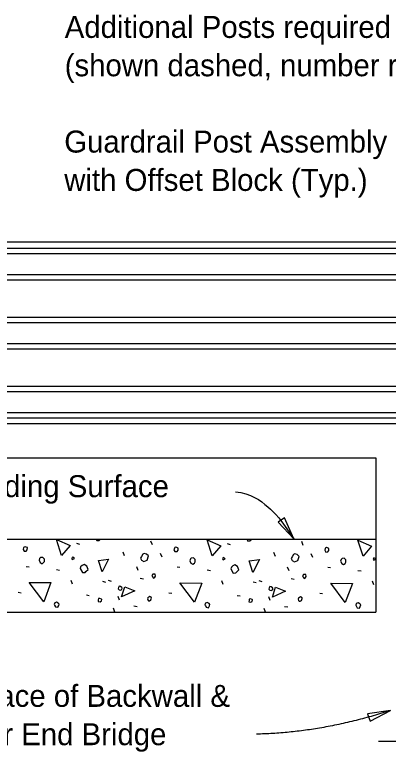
# Model space of a CAD drawing. Extents: x 21587 to 21656.3, y 56114 to 56157.2.
# Drawn here: x 21610.17 to 21613.6, y 56132.08 to 56138.87 of the extents above; entities that cross this region are included whole.
import ezdxf

# ---------------------------------------------------------------- set-up
doc = ezdxf.new("R2010")
doc.units = 0
for name, color, linetype in [('AdhocPoint_dp', 7, 'Continuous'), ('Border', 7, 'Continuous'), ('PlotBorder_dp', 7, 'Continuous'), ('SheetBorder_dp', 7, 'Continuous'), ('TextMisc', 7, 'Continuous')]:
    doc.layers.add(name, color=color, linetype=linetype)

msp = doc.modelspace()

# ---------------------------------------------------------------- linework, layer by layer
at = {"layer": 'AdhocPoint_dp'}
for p, q in [((21607.3117, 56134.8009), (21613.4854, 56134.8009)), ((21613.4854, 56134.8008), (21613.4854, 56133.3842)), ((21613.4854, 56134.0509), (21607.3117, 56134.0509)), ((21607.3117, 56133.3843), (21613.4854, 56133.3843))]:
    msp.add_line(p, q, dxfattribs=at)
at = {"layer": 'Border'}
for p, q in [((21619.5663, 56136.7801), (21607.3117, 56136.7801)), ((21607.3117, 56136.7246), (21619.5663, 56136.7246)), ((21607.3117, 56136.6764), (21619.5663, 56136.6764)), ((21607.3117, 56136.4835), (21619.5663, 56136.4835)), ((21607.3117, 56136.4353), (21619.5663, 56136.4353)), ((21607.3117, 56136.0914), (21619.5663, 56136.0914)), ((21607.3117, 56136.0431), (21619.5663, 56136.0431)), ((21607.3117, 56135.8503), (21619.5663, 56135.8503)), ((21607.3117, 56135.8022), (21619.5663, 56135.8022)), ((21607.3117, 56135.4582), (21619.5663, 56135.4582)), ((21607.3117, 56135.41), (21619.5663, 56135.41)), ((21607.3117, 56135.2172), (21619.5663, 56135.2172)), ((21607.3117, 56135.169), (21619.5663, 56135.169)), ((21619.5663, 56135.1134), (21607.3117, 56135.1134))]:
    msp.add_line(p, q, dxfattribs=at)
at = {"layer": 'PlotBorder_dp'}
for points in [[(21612.7308, 56134.0576), (21612.6444, 56134.2503), (21612.5857, 56134.211)], [(21613.6179, 56132.4823), (21613.4091, 56132.4504), (21613.4313, 56132.3834)]]:
    msp.add_lwpolyline(points, close=True, dxfattribs=at)
msp.add_lwpolyline([(21614.708, 56132.1964), (21614.1994, 56132.1964), (21614.1994, 56132.0801), (21614.1, 56132.3051), (21614.1, 56132.1964), (21613.508, 56132.1964)], dxfattribs=at)
for points, degree in [([(21612.194, 56134.4896), (21612.3358, 56134.4753), (21612.5127, 56134.3451), (21612.6101, 56134.2379), (21612.7308, 56134.0575)], 3), ([(21613.6179, 56132.4823), (21613.0032, 56132.2789), (21612.3886, 56132.2639)], 2)]:
    msp.add_open_spline(points, degree=degree, dxfattribs=at)
at = {"layer": 'TextMisc'}
for p, q in [((21611.4329, 56134.0008), (21611.4187, 56134.0362)), ((21612.8175, 56133.9973), (21612.8034, 56134.0326)), ((21610.7346, 56134.0167), (21610.7629, 56134.0096)), ((21612.1193, 56134.0132), (21612.1476, 56134.0061)), ((21611.1765, 56133.9), (21611.1624, 56133.9354)), ((21611.5206, 56133.8883), (21611.5065, 56133.9237)), ((21612.5612, 56133.8965), (21612.5471, 56133.9319)), ((21612.9053, 56133.8848), (21612.8912, 56133.9201)), ((21610.2738, 56133.8034), (21610.2986, 56133.7999)), ((21610.5496, 56133.7752), (21610.5797, 56133.7699)), ((21611.302, 56133.7675), (21611.2897, 56133.801)), ((21611.6585, 56133.7999), (21611.6833, 56133.7964)), ((21611.9343, 56133.7716), (21611.9643, 56133.7663)), ((21612.6867, 56133.7639), (21612.6743, 56133.7975)), ((21613.0432, 56133.7964), (21613.0679, 56133.7928)), ((21613.319, 56133.7681), (21613.349, 56133.7628)), ((21611.3209, 56133.6956), (21611.3509, 56133.6903)), ((21612.7055, 56133.6921), (21612.7356, 56133.6868)), ((21610.6981, 56133.6408), (21610.6857, 56133.6744)), ((21610.9721, 56133.6673), (21611.0004, 56133.6603)), ((21611.0245, 56133.6773), (21611.0528, 56133.6702)), ((21612.0828, 56133.6373), (21612.0704, 56133.6709)), ((21612.3568, 56133.6638), (21612.3851, 56133.6567)), ((21612.4092, 56133.6738), (21612.4375, 56133.6667)), ((21613.4674, 56133.6337), (21613.4551, 56133.6673)), ((21610.1996, 56133.5666), (21610.2261, 56133.5613)), ((21611.5843, 56133.563), (21611.6108, 56133.5577)), ((21612.9689, 56133.5595), (21612.9955, 56133.5542)), ((21610.8254, 56133.5418), (21610.8519, 56133.5365)), ((21611.1306, 56133.4947), (21611.1182, 56133.5283)), ((21612.21, 56133.5383), (21612.2366, 56133.533)), ((21612.5152, 56133.4912), (21612.5029, 56133.5248)), ((21611.0881, 56133.3851), (21611.074, 56133.4205)), ((21611.2608, 56133.4411), (21611.2926, 56133.4375)), ((21612.6454, 56133.4375), (21612.6773, 56133.434)), ((21612.4717, 56133.3843), (21612.4587, 56133.4169))]:
    msp.add_line(p, q, dxfattribs=at)
for points in [[(21610.5973, 56133.9042), (21610.5496, 56134.0509), (21610.6751, 56133.9961), (21610.5973, 56133.9042)], [(21610.9179, 56134.0509), (21610.922, 56134.0415), (21610.9184, 56134.045)], [(21610.922, 56134.0415), (21610.9432, 56134.0415), (21610.9527, 56134.0509)], [(21611.982, 56133.9007), (21611.9343, 56134.0474), (21612.0598, 56133.9926), (21611.982, 56133.9007)], [(21612.3017, 56134.0509), (21612.3013, 56134.0503), (21612.3067, 56134.0379), (21612.3031, 56134.0415)], [(21612.3067, 56134.0379), (21612.3279, 56134.0379), (21612.3385, 56134.0485), (21612.3378, 56134.0509)], [(21613.3667, 56133.8971), (21613.319, 56134.0439), (21613.4445, 56133.9891), (21613.3667, 56133.8971)], [(21610.2455, 56133.959), (21610.2544, 56133.9431), (21610.2738, 56133.9449), (21610.2827, 56133.9572), (21610.2844, 56133.9767), (21610.2721, 56133.982), (21610.2632, 56133.9838), (21610.2526, 56133.9802), (21610.2491, 56133.9767), (21610.2455, 56133.959)], [(21611.6302, 56133.9555), (21611.6391, 56133.9396), (21611.6585, 56133.9413), (21611.6673, 56133.9537), (21611.6691, 56133.9731), (21611.6567, 56133.9785), (21611.6479, 56133.9802), (21611.6373, 56133.9767), (21611.6338, 56133.9731), (21611.6302, 56133.9555)], [(21613.0149, 56133.9519), (21613.0237, 56133.936), (21613.0432, 56133.9378), (21613.052, 56133.9502), (21613.0538, 56133.9696), (21613.0414, 56133.9749), (21613.0326, 56133.9767), (21613.022, 56133.9731), (21613.0184, 56133.9696), (21613.0149, 56133.9519)], [(21611.3303, 56133.8629), (21611.3533, 56133.8505), (21611.3834, 56133.8629), (21611.3957, 56133.9), (21611.3781, 56133.9177), (21611.3551, 56133.923), (21611.3445, 56133.916), (21611.3321, 56133.8965), (21611.3233, 56133.8806), (21611.3303, 56133.8629)], [(21612.715, 56133.8594), (21612.738, 56133.847), (21612.768, 56133.8594), (21612.7804, 56133.8965), (21612.7627, 56133.9142), (21612.7398, 56133.9195), (21612.7291, 56133.9124), (21612.7168, 56133.893), (21612.7079, 56133.8771), (21612.715, 56133.8594)], [(21610.3905, 56133.86), (21610.4011, 56133.8388), (21610.4188, 56133.8282), (21610.4329, 56133.8388), (21610.44, 56133.8494), (21610.44, 56133.8706), (21610.4241, 56133.8865), (21610.4046, 56133.8848), (21610.3958, 56133.8759), (21610.3905, 56133.86)], [(21610.6963, 56133.8689), (21610.7158, 56133.8777), (21610.7087, 56133.8848), (21610.6963, 56133.8901), (21610.691, 56133.8777), (21610.6963, 56133.8689)], [(21610.9697, 56133.7533), (21610.9361, 56133.8576), (21611.0298, 56133.87), (21610.9697, 56133.7533)], [(21611.7752, 56133.8565), (21611.7858, 56133.8353), (21611.8035, 56133.8247), (21611.8176, 56133.8353), (21611.8247, 56133.8459), (21611.8247, 56133.8671), (21611.8088, 56133.883), (21611.7893, 56133.8812), (21611.7805, 56133.8724), (21611.7752, 56133.8565)], [(21612.081, 56133.8653), (21612.1004, 56133.8742), (21612.0934, 56133.8812), (21612.081, 56133.8865), (21612.0757, 56133.8742), (21612.081, 56133.8653)], [(21612.3544, 56133.7498), (21612.3208, 56133.8541), (21612.4145, 56133.8665), (21612.3544, 56133.7498)], [(21613.1599, 56133.8529), (21613.1705, 56133.8317), (21613.1881, 56133.8211), (21613.2023, 56133.8317), (21613.2094, 56133.8423), (21613.2094, 56133.8635), (21613.1934, 56133.8795), (21613.174, 56133.8777), (21613.1652, 56133.8689), (21613.1599, 56133.8529)], [(21613.4657, 56133.8618), (21613.4851, 56133.8706), (21613.4781, 56133.8777), (21613.4657, 56133.883), (21613.4604, 56133.8706), (21613.4657, 56133.8618)], [(21610.767, 56133.784), (21610.79, 56133.7469), (21610.813, 56133.7486), (21610.8218, 56133.7575), (21610.8413, 56133.7769), (21610.8289, 56133.807), (21610.8042, 56133.8211), (21610.7865, 56133.814), (21610.7723, 56133.7999), (21610.767, 56133.784)], [(21612.1517, 56133.7805), (21612.1747, 56133.7433), (21612.1977, 56133.7451), (21612.2065, 56133.7539), (21612.226, 56133.7734), (21612.2136, 56133.8034), (21612.1888, 56133.8176), (21612.1712, 56133.8105), (21612.157, 56133.7964), (21612.1517, 56133.7805)], [(21611.4322, 56133.708), (21611.4428, 56133.6974), (21611.4534, 56133.7044), (21611.4605, 56133.7151), (21611.457, 56133.7327), (21611.4481, 56133.7345), (21611.4358, 56133.7327), (21611.4252, 56133.7221), (21611.4322, 56133.708)], [(21612.8169, 56133.7044), (21612.8275, 56133.6938), (21612.8381, 56133.7009), (21612.8452, 56133.7115), (21612.8417, 56133.7292), (21612.8328, 56133.731), (21612.8204, 56133.7292), (21612.8098, 56133.7186), (21612.8169, 56133.7044)], [(21610.4347, 56133.4799), (21610.3003, 56133.6567), (21610.5001, 56133.655), (21610.4347, 56133.4799)], [(21611.127, 56133.5889), (21611.1394, 56133.5871), (21611.1518, 56133.5925), (21611.1553, 56133.6031), (21611.15, 56133.6119), (21611.1394, 56133.619), (21611.127, 56133.6243), (21611.12, 56133.6101), (21611.1164, 56133.5995), (21611.127, 56133.5889)], [(21611.8194, 56133.4764), (21611.685, 56133.6532), (21611.8848, 56133.6514), (21611.8194, 56133.4764)], [(21613.2041, 56133.4729), (21613.0697, 56133.6496), (21613.2695, 56133.6479), (21613.2041, 56133.4729)], [(21611.1494, 56133.5241), (21611.1777, 56133.6161), (21611.2714, 56133.5789), (21611.1494, 56133.5241)], [(21612.5117, 56133.5854), (21612.5241, 56133.5836), (21612.5365, 56133.5889), (21612.54, 56133.5995), (21612.5347, 56133.6084), (21612.5241, 56133.6154), (21612.5117, 56133.6207), (21612.5046, 56133.6066), (21612.5011, 56133.596), (21612.5117, 56133.5854)], [(21612.5341, 56133.5206), (21612.5624, 56133.6125), (21612.656, 56133.5754), (21612.5341, 56133.5206)], [(21610.9332, 56133.4835), (21610.9527, 56133.4782), (21610.965, 56133.487), (21610.9668, 56133.4994), (21610.9633, 56133.5029), (21610.9491, 56133.51), (21610.9367, 56133.5082), (21610.935, 56133.4959), (21610.9332, 56133.4835)], [(21611.3969, 56133.4888), (21611.4039, 56133.4888), (21611.4181, 56133.4959), (21611.4234, 56133.5118), (21611.4216, 56133.5206), (21611.4075, 56133.5277), (21611.3898, 56133.5171), (21611.3863, 56133.5065), (21611.3898, 56133.4959), (21611.3969, 56133.4888)], [(21612.3179, 56133.4799), (21612.3373, 56133.4746), (21612.3497, 56133.4835), (21612.3515, 56133.4959), (21612.3479, 56133.4994), (21612.3338, 56133.5065), (21612.3214, 56133.5047), (21612.3197, 56133.4923), (21612.3179, 56133.4799)], [(21612.7816, 56133.4852), (21612.7886, 56133.4852), (21612.8028, 56133.4923), (21612.8081, 56133.5082), (21612.8063, 56133.5171), (21612.7922, 56133.5241), (21612.7745, 56133.5135), (21612.7709, 56133.5029), (21612.7745, 56133.4923), (21612.7816, 56133.4852)], [(21610.5337, 56133.4481), (21610.5425, 56133.4322), (21610.5637, 56133.4287), (21610.5726, 56133.4446), (21610.5761, 56133.4587), (21610.5673, 56133.4676), (21610.5514, 56133.4764), (21610.5355, 56133.4711), (21610.5302, 56133.4552), (21610.5337, 56133.4481)], [(21611.9184, 56133.4446), (21611.9272, 56133.4287), (21611.9484, 56133.4251), (21611.9573, 56133.4411), (21611.9608, 56133.4552), (21611.952, 56133.464), (21611.936, 56133.4729), (21611.9201, 56133.4676), (21611.9148, 56133.4517), (21611.9184, 56133.4446)], [(21613.303, 56133.4411), (21613.3119, 56133.4251), (21613.3331, 56133.4216), (21613.3419, 56133.4375), (21613.3455, 56133.4517), (21613.3366, 56133.4605), (21613.3207, 56133.4693), (21613.3048, 56133.464), (21613.2995, 56133.4481), (21613.303, 56133.4411)]]:
    msp.add_lwpolyline(points, dxfattribs=at)

# ---------------------------------------------------------------- texts
at = {"layer": 'PlotBorder_dp'}
for s, p in [('Additional Posts required for Scheme 6 ', (21610.6265, 56138.6559)), ('(shown dashed, number reqd. varies)', (21610.6265, 56138.3039)), ('Guardrail Post Assembly ', (21610.6223, 56137.6034)), ('with Offset Block (Typ.)', (21610.6223, 56137.2514)), ('Front Face of Backwall &', (21609.1479, 56132.5148)), ('Begin or End Bridge', (21609.1479, 56132.1628))]:
    msp.add_text(s, height=0.2016, dxfattribs=at).set_placement(p)
at = {"layer": 'SheetBorder_dp'}
msp.add_text('Final Riding Surface', height=0.2016, dxfattribs=at).set_placement((21609.1559, 56134.44))

doc.saveas('drawing.dxf')
